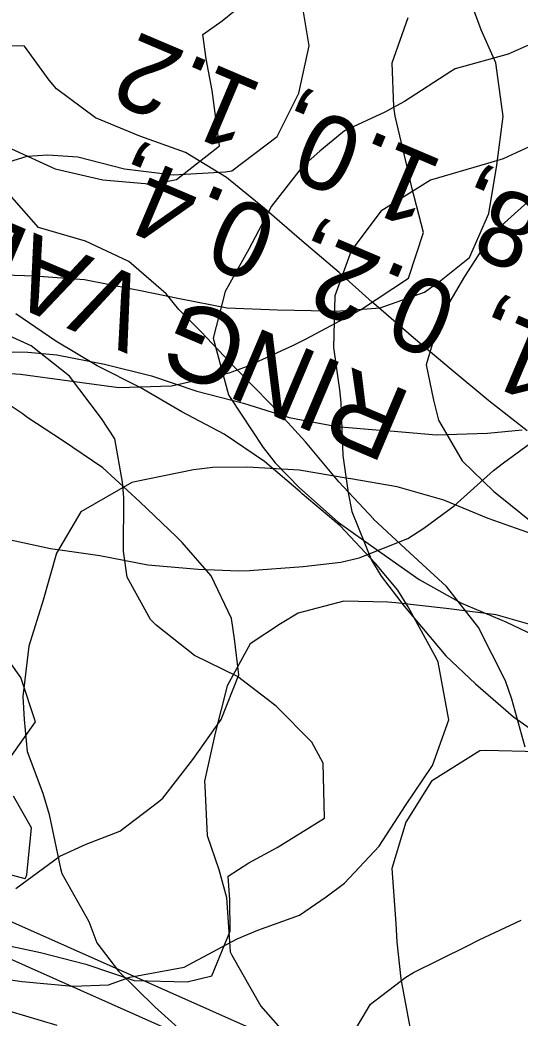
# Model space of a CAD drawing. Extents: x 1638506 to 1658005, y 834807 to 846788.
# Drawn here: x 1639827.3 to 1639907.1, y 842760 to 842919.2 of the extents above; entities that cross this region are included whole.
import ezdxf

# ---------------------------------------------------------------- set-up
doc = ezdxf.new("R2010")
doc.units = 0
for name, color, linetype in [('Default', 7, 'Continuous'), ('Old_Level_1', 7, 'Continuous'), ('Old_Level_2', 7, 'Continuous'), ('Scratch_Level_0', 7, 'Continuous')]:
    doc.layers.add(name, color=color, linetype=linetype)

msp = doc.modelspace()

# ---------------------------------------------------------------- linework, layer by layer
at = {"layer": 'Default'}
msp.add_line((1639782.61, 842788.6), (1640040.31, 842674.21), dxfattribs=at)
at = {"layer": 'Old_Level_1'}
for points in [[(1639819.25, 842894.62), (1639828.42, 842897.43), (1639831.71, 842897.64), (1639836.53, 842897.35), (1639843.97, 842895.43), (1639851.75, 842894.44), (1639860.08, 842894.95), (1639861.06, 842895.1), (1639868.3, 842900.6), (1639871.79, 842907.47), (1639873.41, 842915.02), (1639871.99, 842923.68)], [(1639821.58, 842878.64), (1639829.62, 842878.35), (1639837.55, 842877.78), (1639845.14, 842876.27), (1639846.24, 842876.07), (1639852.72, 842874.73), (1639860.33, 842873.26), (1639868.35, 842872.95), (1639876.43, 842872.78), (1639877.74, 842872.74), (1639884.74, 842873.24), (1639891.83, 842875.76), (1639894.5, 842877.68), (1639899.02, 842881.28), (1639902.09, 842888.3), (1639903.35, 842895.99), (1639904.36, 842903.76), (1639904.27, 842904.54), (1639903.19, 842912.32), (1639900.87, 842917.56), (1639899.27, 842921.89)], [(1639908.5, 842915.2), (1639905.17, 842913.7), (1639896.72, 842911.35), (1639896.02, 842910.92), (1639888.65, 842906.14), (1639885.52, 842904.44), (1639879.08, 842901.49), (1639875.12, 842898.22), (1639872.38, 842895.79), (1639867.41, 842889.45), (1639863.79, 842882.63), (1639860.02, 842875.86), (1639858.1, 842868.42), (1639860.56, 842859.38)], [(1639908.84, 842890.65), (1639903.01, 842885.39), (1639902.45, 842884.84), (1639898.22, 842878.24), (1639894.25, 842871.54), (1639892.09, 842864.19)], [(1639894.01, 842816.78), (1639893.78, 842817.23), (1639889.24, 842825.61), (1639887.56, 842828.23), (1639884.03, 842832.52), (1639878.38, 842838.5), (1639872.33, 842843.63), (1639871.99, 842843.94), (1639866.28, 842848.77), (1639859.87, 842853.12), (1639853.09, 842856.68), (1639846.46, 842860.57), (1639839.62, 842863.99), (1639833.02, 842867.94), (1639826.6, 842872.28)], [(1639825.2, 842866.23), (1639828.55, 842866.22), (1639833.17, 842865.76), (1639840.78, 842864.29), (1639848.24, 842862.42), (1639855.5, 842860), (1639862.94, 842858.06), (1639870.24, 842855.77), (1639877.86, 842854.32), (1639885.31, 842853.71), (1639885.76, 842853.68), (1639893.67, 842853.03), (1639901.9, 842853.27), (1639907.42, 842853.8)], [(1639892.09, 842864.19), (1639893.24, 842858.53), (1639894.04, 842855.34), (1639897.85, 842848.85), (1639902.9, 842843.97), (1639903.92, 842843.16), (1639910.22, 842838.1)], [(1639862.19, 842814.74), (1639861.53, 842820.48), (1639861.01, 842823.73), (1639857.78, 842830.53), (1639853.17, 842835.83), (1639852.23, 842836.73), (1639846.39, 842842.32), (1639840.5, 842847.77), (1639834.08, 842852.11), (1639828.55, 842855.75), (1639827.63, 842856.39), (1639821.19, 842860.68)], [(1639860.56, 842859.38), (1639860.83, 842858.96), (1639866.08, 842851.01), (1639867.98, 842848.54), (1639871.88, 842844.58), (1639878.03, 842839.11), (1639884.5, 842834.53), (1639884.86, 842834.25), (1639890.97, 842829.94), (1639897.73, 842826.16), (1639904.8, 842823.21), (1639911.74, 842819.91)], [(1639909.23, 842837.12), (1639901.99, 842839.7), (1639894.91, 842842.61), (1639887.45, 842844.72), (1639880.08, 842845.99), (1639879.63, 842846.05), (1639871.81, 842847.39), (1639863.6, 842847.87), (1639858.05, 842847.82), (1639854.95, 842847.42), (1639845.62, 842845.52), (1639845.12, 842845.41), (1639836.99, 842840.76), (1639833.09, 842834.13), (1639830.97, 842826.68), (1639828.7, 842819.3), (1639827.74, 842811.31), (1639827.96, 842807.65), (1639828.45, 842802.54), (1639830.92, 842795.89), (1639831.93, 842792.48), (1639833.76, 842783.88), (1639833.95, 842783.09), (1639838.27, 842775.45), (1639839.56, 842772.04), (1639843.01, 842767.52), (1639848.8, 842761.84), (1639854.71, 842756.53)], [(1639910.71, 842822.2), (1639903.26, 842824.33), (1639895.3, 842825.34), (1639887.26, 842826.22), (1639885.97, 842826.36), (1639878.95, 842826.48), (1639871.67, 842824.59), (1639868.84, 842822.9), (1639864.02, 842819.71), (1639860.35, 842812.98), (1639858.43, 842805.44), (1639856.74, 842797.78), (1639856.76, 842797), (1639857.16, 842789.15), (1639859.01, 842783.73), (1639860.23, 842779.28), (1639860.8, 842770.57), (1639861.07, 842770.05), (1639865.73, 842761.94), (1639868.85, 842758.38)], [(1639819.77, 842766.99), (1639827.63, 842765.88), (1639835.71, 842765.1), (1639841.39, 842765.36), (1639844.83, 842766.57), (1639853.46, 842768.17), (1639854.19, 842768.53), (1639861.95, 842772.65), (1639865.21, 842774.07), (1639871.89, 842776.45), (1639876.12, 842779.36), (1639879.07, 842781.55), (1639884.57, 842787.42), (1639888.77, 842793.91), (1639893.11, 842800.32), (1639895.68, 842807.57), (1639894.01, 842816.78)], [(1639826.61, 842780.69), (1639833.65, 842785.85), (1639837.84, 842787.78), (1639843.19, 842789.84), (1639849.45, 842794.58), (1639850.06, 842795.07), (1639854.85, 842801.28), (1639859.39, 842807.61), (1639862.19, 842814.74)], [(1639909.96, 842802.49), (1639901.62, 842802.7), (1639900.63, 842802.64), (1639892.94, 842797.79), (1639888.87, 842791.25), (1639886.59, 842783.87), (1639887.25, 842775.12), (1639887.39, 842772.19), (1639888.07, 842766.3), (1639889.5, 842758.6), (1639890.17, 842756.88), (1639895.29, 842752.92), (1639901.96, 842749.12), (1639908.95, 842746.02)]]:
    msp.add_lwpolyline(points, dxfattribs=at)
at = {"layer": 'Old_Level_2'}
msp.add_line((1639680.46, 842839.86), (1639907.01, 842739.41), dxfattribs=at)
at = {"layer": 'Scratch_Level_0'}
for points in [[(1639908.21, 842853.63), (1639902.07, 842858.41), (1639896.06, 842863.44), (1639890.06, 842868.47), (1639884.12, 842873.64), (1639883.49, 842874.18), (1639878.21, 842878.87), (1639872.24, 842883.96), (1639866.28, 842889.09), (1639860.23, 842894.04), (1639853.68, 842898.01), (1639846.42, 842900.65), (1639839.32, 842903.56), (1639833.09, 842908.17), (1639831.92, 842909.58), (1639828, 842914.97), (1639821.34, 842915.08), (1639819.51, 842915.22), (1639812.16, 842917.67), (1639805.69, 842921.8)], [(1639825.94, 842898.61), (1639832.9, 842895.42), (1639840.48, 842893.69), (1639848.48, 842892.97), (1639852.25, 842893.71), (1639859.11, 842899.11), (1639857.93, 842907.92), (1639856.96, 842912.97), (1639856.47, 842916.84), (1639859.54, 842919.04), (1639863.46, 842922.19)], [(1639819.25, 842863.23), (1639827.34, 842862.71), (1639827.37, 842862.71), (1639835.2, 842861.65), (1639843.05, 842860.57), (1639851.43, 842860.82), (1639851.47, 842860.82), (1639860.66, 842862.91), (1639863.56, 842863.98), (1639870.81, 842867.24), (1639872.93, 842868.32), (1639881.52, 842872.9), (1639881.6, 842872.95), (1639889.26, 842878.01), (1639891.69, 842885.29), (1639889.8, 842892.43), (1639889.3, 842894.61), (1639887.16, 842903.83), (1639886.95, 842905.29), (1639886.68, 842912.34), (1639889.23, 842919.57)], [(1639912, 842900.52), (1639904.37, 842897.02), (1639901.88, 842896.27), (1639892.77, 842893.63), (1639892.34, 842893.35), (1639884.88, 842888.67), (1639880.14, 842882.37), (1639877.52, 842875.17), (1639877.31, 842866.95)], [(1639907.88, 842803.22), (1639905.78, 842810.88), (1639904.76, 842813.79), (1639900.51, 842822.21), (1639900.49, 842822.25), (1639895.34, 842828.86), (1639889.51, 842834.22), (1639883.71, 842839.58), (1639883.68, 842839.61), (1639878.13, 842845.52), (1639872.83, 842851.91), (1639869.41, 842855.63), (1639867.31, 842857.88), (1639861.68, 842863.63), (1639856.11, 842869.5), (1639852.62, 842872.97), (1639850.61, 842875.51), (1639844.65, 842880.63), (1639837.73, 842883.91), (1639830.23, 842886.06), (1639824.82, 842892.24)], [(1639875.66, 842800.66), (1639873.83, 842804.03), (1639868.17, 842809.75), (1639862.01, 842814.48), (1639855.12, 842817.82), (1639849.03, 842822.68), (1639848.12, 842823.58), (1639844.38, 842830.32), (1639843.77, 842834.46), (1639843.87, 842843.03), (1639843.64, 842845.49), (1639842.43, 842852.4), (1639840.28, 842855.62), (1639835.18, 842862.39), (1639829.05, 842867.19), (1639822.07, 842870.35)], [(1639877.31, 842866.95), (1639878.26, 842860.17), (1639878.47, 842858.15), (1639878.8, 842849.7), (1639879.62, 842843.77), (1639880.22, 842840.79), (1639883.38, 842833.04), (1639884.93, 842830.48), (1639888.57, 842825.69), (1639894.09, 842819.11), (1639895.25, 842817.79), (1639899.94, 842813.32), (1639906.02, 842808.06), (1639912.43, 842803.57)], [(1639824.56, 842836.56), (1639832.15, 842834.87), (1639835.2, 842834.46), (1639840, 842833.79), (1639847.68, 842832.31), (1639855.69, 842831.6), (1639862.17, 842831.33), (1639863.92, 842831.41), (1639872.49, 842832.02), (1639878.46, 842832.73), (1639881.38, 842833.39), (1639889.15, 842836.51), (1639891.71, 842838.16), (1639896.54, 842841.69), (1639902.84, 842847.32), (1639904.44, 842848.57), (1639909.98, 842852.6)], [(1639683.93, 842839.91), (1639685.05, 842838.92), (1639690.89, 842833.54), (1639697.36, 842829.42), (1639703.48, 842824.6), (1639709.93, 842820.42), (1639717.06, 842817.56), (1639723.86, 842814.04), (1639730.14, 842809.54), (1639736.71, 842805.59), (1639743.16, 842801.41), (1639750, 842797.99), (1639756.88, 842794.64), (1639763.7, 842791.17), (1639770.46, 842787.59), (1639777.16, 842783.88), (1639783.89, 842780.26), (1639791.02, 842777.38), (1639798.03, 842774.28), (1639805.32, 842771.73), (1639812.11, 842768.19), (1639818.55, 842764), (1639825.68, 842761.13), (1639833.14, 842758.9)], [(1639825.3, 842800.95), (1639829.75, 842807.26), (1639827.44, 842814.31), (1639824.26, 842818.74)], [(1639822.77, 842772.12), (1639830.55, 842770.51), (1639837.78, 842768.61), (1639838.13, 842768.51), (1639845.48, 842766.05), (1639853.97, 842765.81), (1639857.88, 842766.79), (1639860.84, 842773.88), (1639860.77, 842778.9), (1639860.51, 842782.67), (1639863.81, 842784.76), (1639868.33, 842787.23), (1639875.87, 842791.93), (1639875.66, 842800.66)], [(1639828.13, 842782.25), (1639828.35, 842782.87), (1639829.11, 842790.36), (1639826.26, 842795.43)], [(1639820.48, 842784.3), (1639828.03, 842782.26), (1639828.13, 842782.25)], [(1639879.28, 842755.68), (1639883.22, 842762.25), (1639888.83, 842766.53), (1639890.09, 842767.3), (1639898.57, 842771.52), (1639900.56, 842772.52), (1639907.27, 842775.62)]]:
    msp.add_lwpolyline(points, dxfattribs=at)

# ---------------------------------------------------------------- texts
for s, p in [('GE ERL2x23C340', (1639978.02, 842924.85)), ('0.8, 1.0, 1.2', (1639923.93, 842884.33)), ('RING VALUES', (1639890.17, 842859.54)), ('0.1, 0.2, 0.4,', (1639926.63, 842863.63))]:
    msp.add_text(s, height=12, rotation=157.0176, dxfattribs=at).set_placement(p)

doc.saveas('drawing.dxf')
